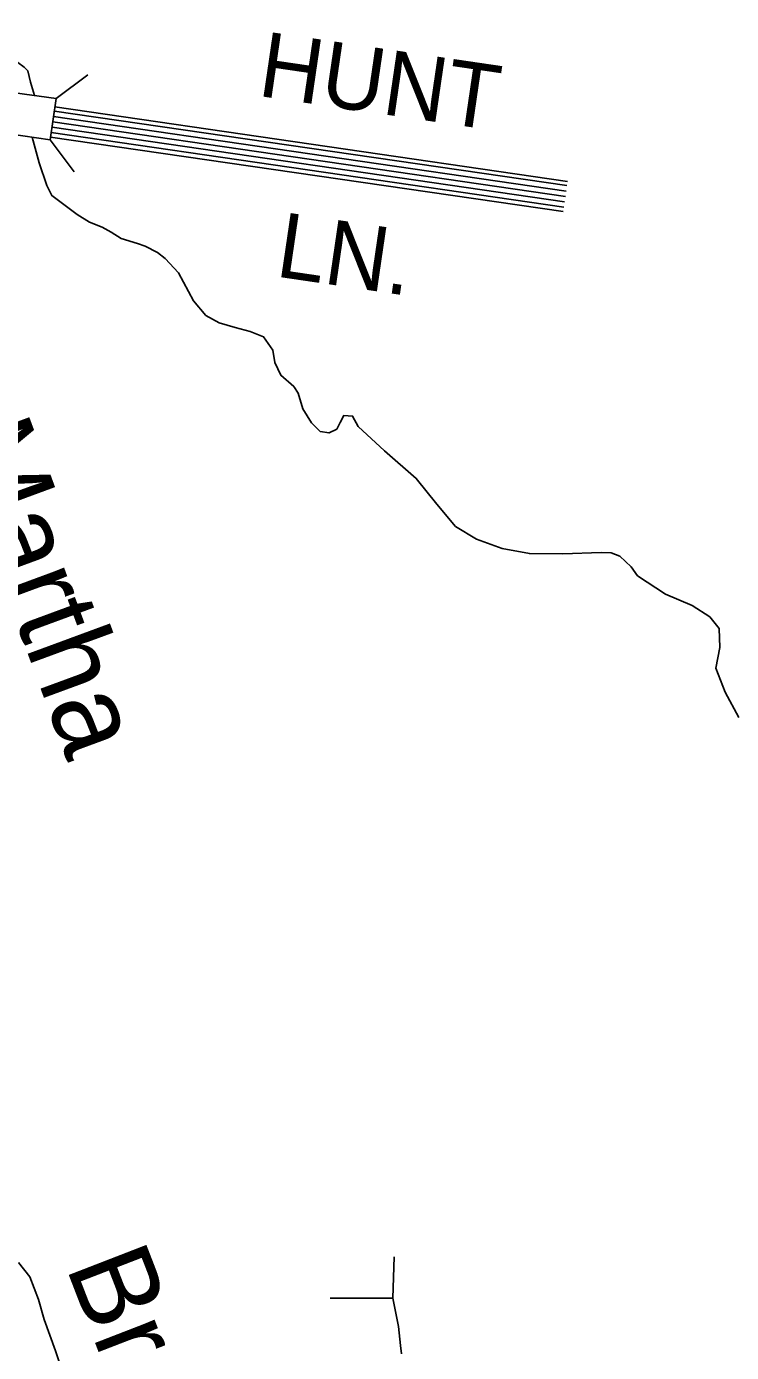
# Model space of a CAD drawing. Extents: x 1788175 to 1969470, y 584502 to 738744.
# Drawn here: x 1847341 to 1851363, y 681239 to 688798 of the extents above; entities that cross this region are included whole.
import ezdxf

# ---------------------------------------------------------------- set-up
doc = ezdxf.new("R2010")
doc.units = 0
for name, color, linetype in [('DESIGN - DRAINAGE - Bridges and Cross Drains Size Text', 7, 'Continuous'), ('DESIGN - ROW - Right-of-Way and Easement Labels', 7, 'Continuous'), ('DESIGN - TRANSPORTATION - Text', 7, 'Continuous'), ('SURVEY - DRAINAGE - Storm Sewer', 7, 'Continuous'), ('SURVEY - TRANSPORTATION - Roads', 7, 'Continuous')]:
    doc.layers.add(name, color=color, linetype=linetype)

msp = doc.modelspace()

# ---------------------------------------------------------------- linework, layer by layer
at = {"layer": 'DESIGN - TRANSPORTATION - Text'}
for points in [[(1846666.3, 688797.6), (1846718.4, 688782.7), (1846778, 688767.7), (1846874.6, 688731.5), (1846996.8, 688710), (1847126.1, 688702.8), (1847219.5, 688645.3), (1847327.3, 688566.3), (1847348.8, 688544.7), (1847363.2, 688480.1), (1847386.5, 688404.2)], [(1847373.2, 688166.1), (1847413.5, 688020.3), (1847456.6, 687891), (1847485.3, 687833.5), (1847629, 687725.7), (1847700.9, 687682.6), (1847772.7, 687653.9), (1847823, 687625.1), (1847880.5, 687589.2), (1847973.9, 687560.5), (1848017, 687546.1), (1848088.8, 687510.2), (1848131.9, 687474.3), (1848208.5, 687394.3)], [(1848208.5, 687394.3), (1848293.1, 687233.6), (1848364.5, 687151), (1848440, 687108.4), (1848531.7, 687081.8), (1848617.5, 687059.1), (1848693.1, 687028.6), (1848746.5, 686952.1), (1848758, 686882), (1848791.5, 686809.7), (1848864.9, 686745.1), (1848890.6, 686706.9), (1848917.9, 686618.6), (1848967.3, 686538.2), (1849016.9, 686489.8), (1849066.8, 686481.4), (1849110.8, 686503.1), (1849131.1, 686541), (1849151.3, 686580.9), (1849201.3, 686576.6), (1849232.8, 686518.3), (1849383.6, 686379.1), (1849564.2, 686221.7), (1849681, 686074.7), (1849788, 685947.8), (1849907.3, 685874.9), (1850054.8, 685821.8), (1850210.3, 685792.7), (1850400.1, 685791.3), (1850619.9, 685799.8), (1850675.8, 685797.4), (1850725.6, 685779), (1850791, 685718.5), (1850826.6, 685666.2), (1850985.7, 685561), (1851139, 685497.8), (1851238.4, 685433.1), (1851291.9, 685366.6), (1851297.1, 685258.5), (1851274.3, 685140.6), (1851327.3, 685004.1), (1851404.1, 684859.4)], [(1847295.4, 681752.4), (1847360.4, 681671.1), (1847409.2, 681540.9), (1847441.8, 681427.1), (1847506.8, 681248.1), (1847588.2, 681004.1)]]:
    msp.add_lwpolyline(points, dxfattribs=at)
at = {"layer": 'SURVEY - DRAINAGE - Storm Sewer'}
for p, q in [((1847509.8, 688386.6), (1847691.5, 688522.8)), ((1847476.1, 688151.4), (1847612.4, 687969.7))]:
    msp.add_line(p, q, dxfattribs=at)
msp.add_lwpolyline([(1847241, 688185), (1847476.2, 688151.4), (1847509.8, 688386.6), (1847274.6, 688420.1)], close=True, dxfattribs=at)
at = {"layer": 'SURVEY - TRANSPORTATION - Roads'}
for points in [[(1847495.2, 688284.6), (1850419.3, 687859.9)], [(1847499.6, 688315.3), (1850423.7, 687890.6)], [(1847503.1, 688339.7), (1850427.3, 687915)], [(1847482.1, 688192.5), (1850405.9, 687767.8)], [(1847486.4, 688223.2), (1850410.4, 687798.5)], [(1847490.8, 688253.9), (1850414.8, 687829.2)], [(1847490.8, 688253.9), (1850414.8, 687829.2)], [(1847478.4, 688167.1), (1850402.2, 687742.4)], [(1849479.4, 681230.9), (1849474.9, 681278.2), (1849463.6, 681386.5), (1849431.5, 681549.5), (1849438.3, 681784.9)], [(1849431.5, 681549.5), (1849072.8, 681549.1)]]:
    msp.add_lwpolyline(points, dxfattribs=at)

# ---------------------------------------------------------------- texts
at = {"layer": 'DESIGN - DRAINAGE - Bridges and Cross Drains Size Text'}
for s, rotation, p in [('Martha', 290.22344, (1846893.1, 686455.4)), ('Br.', 291.15901, (1847562.9, 681729.8))]:
    msp.add_text(s, height=475, rotation=rotation, dxfattribs=at).set_placement(p)
at = {"layer": 'DESIGN - ROW - Right-of-Way and Easement Labels'}
for s, p in [('HUNT', (1848652.6, 688403.5)), ('LN.', (1848753.9, 687373.9))]:
    msp.add_text(s, height=370, rotation=351.65092, dxfattribs=at).set_placement(p)

doc.saveas('drawing.dxf')
